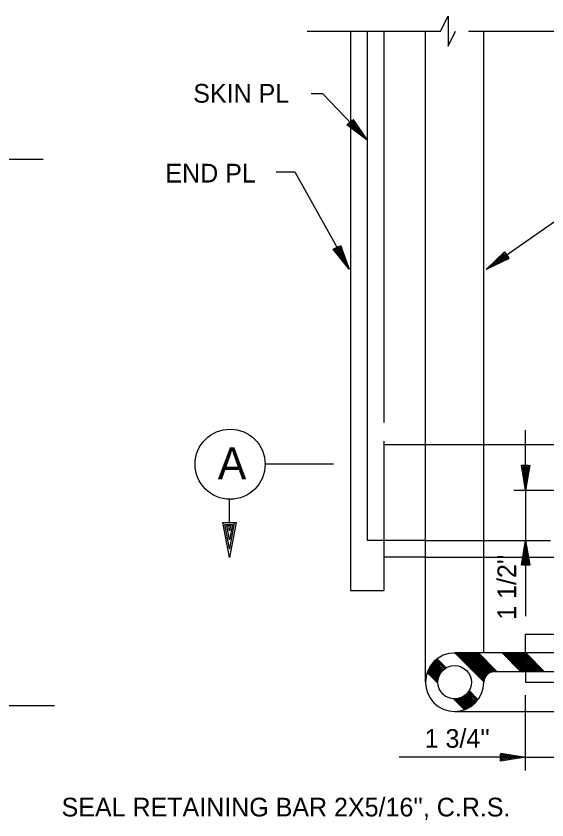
# Model space of a CAD drawing. Extents: x 0.1 to 13.5, y 0.1 to 9.5.
# Drawn here: x 7.414 to 8.739, y 2.991 to 4.998 of the extents above; entities that cross this region are included whole.
import ezdxf

# ---------------------------------------------------------------- set-up
doc = ezdxf.new("R2010")
doc.units = 0
for name, color, linetype in [('Level 13', 7, 'Continuous'), ('Level 25', 7, 'Continuous'), ('Level 3', 7, 'Continuous'), ('Level 50', 7, 'Continuous')]:
    doc.layers.add(name, color=color, linetype=linetype)

msp = doc.modelspace()

# ---------------------------------------------------------------- linework, layer by layer
at = {"layer": 'Level 13'}
for p, q in [((8.4652, 3.3928), (8.4877, 3.3703)), ((8.9568, 3.4074), (8.5089, 3.4074)), ((8.5096, 3.4074), (8.5818, 3.3352)), ((8.5133, 3.4074), (8.5821, 3.3385)), ((8.517, 3.4074), (8.5828, 3.3415)), ((8.5206, 3.4074), (8.5837, 3.3443)), ((8.5243, 3.4074), (8.5849, 3.3468)), ((8.528, 3.4074), (8.586, 3.3493)), ((8.5317, 3.4074), (8.5879, 3.3512)), ((8.5354, 3.4074), (8.5898, 3.353)), ((8.5391, 3.4074), (8.5916, 3.3548)), ((8.5427, 3.4074), (8.5938, 3.3564)), ((8.5464, 3.4074), (8.5961, 3.3577)), ((8.5501, 3.4074), (8.5986, 3.3588)), ((8.5538, 3.4074), (8.6014, 3.3597)), ((8.5575, 3.4074), (8.6046, 3.3603)), ((8.5612, 3.4074), (8.608, 3.3605)), ((8.5648, 3.4074), (8.6117, 3.3605)), ((8.5685, 3.4074), (8.6154, 3.3605)), ((8.6274, 3.4074), (8.6743, 3.3605)), ((8.6311, 3.4074), (8.678, 3.3605)), ((8.6348, 3.4074), (8.6817, 3.3605)), ((8.6385, 3.4074), (8.6854, 3.3605)), ((8.6422, 3.4074), (8.689, 3.3605)), ((8.6422, 3.4074), (8.6854, 3.3642)), ((8.6459, 3.4074), (8.6927, 3.3605)), ((8.6495, 3.4074), (8.6964, 3.3605)), ((8.6532, 3.4074), (8.7001, 3.3605)), ((8.6569, 3.4074), (8.7038, 3.3605)), ((8.6606, 3.4074), (8.7075, 3.3605)), ((8.6643, 3.4074), (8.7111, 3.3605)), ((8.668, 3.4074), (8.7148, 3.3605)), ((8.6716, 3.4074), (8.7185, 3.3605)), ((8.6753, 3.4074), (8.7222, 3.3605)), ((8.679, 3.4074), (8.7259, 3.3605)), ((8.6827, 3.4074), (8.7296, 3.3605)), ((8.6864, 3.4074), (8.7332, 3.3605)), ((8.4475, 3.3738), (8.4705, 3.3507)), ((8.4489, 3.376), (8.4717, 3.3532)), ((8.4505, 3.3781), (8.473, 3.3556)), ((8.4521, 3.3802), (8.4741, 3.3581)), ((8.4538, 3.3822), (8.476, 3.36)), ((8.4555, 3.3842), (8.4776, 3.3621)), ((8.4573, 3.386), (8.4794, 3.3639)), ((8.4593, 3.3877), (8.4813, 3.3657)), ((8.4611, 3.3896), (8.4833, 3.3674)), ((8.4631, 3.3912), (8.4854, 3.3689)), ((8.4402, 3.3589), (8.4673, 3.3318)), ((8.4412, 3.3616), (8.4672, 3.3356)), ((8.4423, 3.3642), (8.4675, 3.339)), ((8.4435, 3.3667), (8.4679, 3.3422)), ((8.4447, 3.3691), (8.4686, 3.3452)), ((8.4461, 3.3715), (8.4695, 3.348)), ((8.9568, 3.3605), (8.6079, 3.3605)), ((8.5448, 3.3133), (8.5673, 3.2908)), ((8.5063, 3.2929), (8.5334, 3.2658)), ((8.51, 3.2928), (8.536, 3.2668)), ((8.5135, 3.293), (8.5386, 3.2679)), ((8.5167, 3.2935), (8.5411, 3.269)), ((8.5197, 3.2942), (8.5436, 3.2703)), ((8.5225, 3.2951), (8.5459, 3.2716)), ((8.5251, 3.2961), (8.5482, 3.273)), ((8.5276, 3.2973), (8.5504, 3.2745)), ((8.53, 3.2986), (8.5525, 3.276)), ((8.5323, 3.3), (8.5546, 3.2777)), ((8.5344, 3.3015), (8.5566, 3.2793)), ((8.5365, 3.3031), (8.5586, 3.281)), ((8.5383, 3.305), (8.5604, 3.2829)), ((8.5401, 3.3069), (8.5621, 3.2849)), ((8.5418, 3.3089), (8.564, 3.2867)), ((8.5433, 3.311), (8.5654, 3.2889))]:
    msp.add_line(p, q, dxfattribs=at)
msp.add_lwpolyline([(8.474, 4.9602), (8.4926, 4.9977), (8.4926, 4.9228), (8.5114, 4.9602)], dxfattribs=at)
msp.add_circle((8.5089, 3.3344), 0.0417, dxfattribs=at)
for centre, radius, end in [((8.5089, 3.3344), 0.0729, 0), ((8.6078, 3.3344), 0.026, 180)]:
    msp.add_arc(centre, radius, 90, end, dxfattribs=at)
at = {"layer": 'Level 25'}
for p, q in [((8.1404, 4.9602), (8.474, 4.9602)), ((8.2492, 4.9602), (8.2492, 3.5636)), ((8.2909, 4.9602), (8.2909, 3.6886)), ((8.3325, 4.9602), (8.3325, 3.9829)), ((8.436, 3.3344), (8.436, 4.9602)), ((8.5432, 4.9602), (9.5474, 4.9602)), ((8.5818, 3.4074), (8.5818, 4.9602)), ((4.8601, 4.6407), (7.482, 4.6407)), ((8.3325, 3.9829), (8.3325, 3.9829)), ((8.686, 3.8136), (8.686, 3.9639)), ((8.3325, 3.936), (8.3325, 3.6886)), ((8.3325, 3.9282), (10.9683, 3.9282)), ((8.6565, 3.8136), (10.9683, 3.8136)), ((8.686, 3.8136), (8.686, 3.6886)), ((8.436, 3.6886), (8.2909, 3.6886)), ((8.3325, 3.6886), (8.3325, 3.6886)), ((8.3325, 3.6886), (8.3325, 3.5636)), ((8.436, 3.6886), (8.7485, 3.6886)), ((8.686, 3.6886), (8.686, 3.4989)), ((8.436, 3.647), (8.3325, 3.647)), ((8.436, 3.647), (10.9683, 3.647)), ((8.2492, 3.5636), (8.3325, 3.5636)), ((8.686, 3.4074), (8.686, 3.4543)), ((8.686, 3.4543), (10.9683, 3.4543)), ((8.686, 3.3592), (8.686, 3.3345)), ((8.686, 3.3345), (10.9683, 3.3345)), ((8.686, 3.1136), (8.686, 3.3018)), ((6.6368, 3.276), (7.5102, 3.276)), ((8.5089, 3.2615), (10.9683, 3.2615)), ((8.686, 3.1473), (8.3704, 3.1473)), ((8.686, 3.1473), (8.8318, 3.1473))]:
    msp.add_line(p, q, dxfattribs=at)
at = {"layer": 'Level 3'}
for p, q in [((8.2787, 4.7007), (8.2787, 4.7007)), ((8.2907, 4.6881), (8.2907, 4.6881)), ((8.2368, 4.3813), (8.2368, 4.3813)), ((8.2452, 4.3661), (8.2452, 4.3661)), ((8.5879, 4.365), (8.5879, 4.365)), ((8.6021, 4.3749), (8.6021, 4.3749)), ((8.2061, 3.8787), (8.0341, 3.8787)), ((7.9467, 3.7329), (7.9467, 3.7912))]:
    msp.add_line(p, q, dxfattribs=at)
for points in [[(8.1508, 4.8048), (8.1788, 4.8048), (8.2907, 4.6881)], [(8.255, 4.7403), (8.2907, 4.6881), (8.2401, 4.726), (8.2528, 4.7382), (8.2787, 4.7007), (8.2443, 4.7264), (8.2525, 4.7342), (8.2671, 4.7127), (8.2486, 4.7268), (8.2519, 4.73), (8.2551, 4.7252)], [(9.1101, 4.687), (9.0495, 4.687), (8.5879, 4.365)], [(8.0633, 4.6088), (8.11, 4.6088), (8.2452, 4.3661)], [(8.2239, 4.4256), (8.2452, 4.3661), (8.2058, 4.4156), (8.2213, 4.4241), (8.2368, 4.3813), (8.21, 4.4148), (8.2199, 4.4204), (8.2286, 4.3958), (8.2143, 4.4141), (8.2183, 4.4164), (8.2202, 4.411)], [(8.6449, 4.3921), (8.5879, 4.365), (8.6331, 4.4091), (8.6432, 4.3946), (8.6021, 4.3749), (8.6328, 4.4048), (8.6393, 4.3955), (8.6158, 4.3844), (8.6326, 4.4006), (8.6352, 4.3968), (8.63, 4.3943)], [(7.9589, 3.7329), (7.9633, 3.7329), (7.9467, 3.6454), (7.9304, 3.7329), (7.9589, 3.7329), (7.947, 3.6677), (7.9353, 3.7286), (7.9541, 3.7286), (7.947, 3.6897), (7.9404, 3.7246), (7.9492, 3.7246), (7.947, 3.712), (7.9454, 3.7203)]]:
    msp.add_lwpolyline(points, dxfattribs=at)
msp.add_circle((7.9484, 3.8787), 0.0875, dxfattribs=at)
at = {"layer": 'Level 50'}
for p, q in [((8.686, 3.831), (8.686, 3.831)), ((8.686, 3.8136), (8.686, 3.8136)), ((8.686, 3.6886), (8.686, 3.6886)), ((8.686, 3.6713), (8.686, 3.6713)), ((8.6686, 3.1473), (8.6686, 3.1473)), ((8.686, 3.1473), (8.686, 3.1473))]:
    msp.add_line(p, q, dxfattribs=at)
for points in [[(8.6963, 3.876), (8.686, 3.8136), (8.6756, 3.876), (8.6933, 3.876), (8.686, 3.831), (8.679, 3.8733), (8.6903, 3.8733), (8.686, 3.8476), (8.6823, 3.8706), (8.687, 3.8706), (8.686, 3.865)], [(8.6756, 3.6263), (8.686, 3.6886), (8.6963, 3.6263), (8.6786, 3.6263), (8.686, 3.6713), (8.693, 3.629), (8.6816, 3.629), (8.686, 3.6546), (8.6896, 3.6316), (8.685, 3.6316), (8.686, 3.6373)], [(8.6236, 3.1576), (8.686, 3.1473), (8.6236, 3.1369), (8.6236, 3.1546), (8.6686, 3.1473), (8.6263, 3.1403), (8.6263, 3.1516), (8.652, 3.1473), (8.629, 3.1436), (8.629, 3.1483), (8.6346, 3.1473)]]:
    msp.add_lwpolyline(points, dxfattribs=at)

# ---------------------------------------------------------------- texts
at = {"layer": 'Level 25'}
for s, height, p in [('SKIN PL', 0.0467, (7.8564, 4.7815)), ('END PL', 0.0467, (7.7869, 4.5821)), ('A', 0.08, (7.9175, 3.8408)), ("1 3/4''", 0.0467, (8.434, 3.1706)), ("SEAL RETAINING BAR 2X5/16'', C.R.S.", 0.046698, (7.5277, 2.9992))]:
    msp.add_text(s, height=height, dxfattribs=at).set_placement(p)
msp.add_text("1 1/2''", height=0.0467, rotation=90, dxfattribs=at).set_placement((8.6625, 3.4903))

doc.saveas('drawing.dxf')
